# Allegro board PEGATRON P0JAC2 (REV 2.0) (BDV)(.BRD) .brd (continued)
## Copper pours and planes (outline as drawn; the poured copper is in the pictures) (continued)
+VSYS on L6-GND (solid shape): 60.99,41.82 60.99,39.56 60.83,39.41 60.5,39.41 60.43,39.48 60.43,39.56 60.45,39.63 60.45,39.71 60.45,40.07 60.25,40.27 60.25,41.87 60.33,41.95 60.86,41.95
+VSYS on L6-GND (solid shape): 58.5,41.74 58.5,41.09 58.48,41.08 58.48,40.29 58.49,40.25 58.5,40.17 58.26,39.93 58.26,39.25 58.12,39.11 57.94,39.11 57.81,39.24 57.81,41.74 57.89,41.82 58.42,41.82
+VSYS on L6-GND (solid shape): 56.13,42.91 56.13,39.81 56.07,39.75 55.64,39.75 55.53,39.86 55.53,41.1 55.53,41.11 55.56,41.2 55.56,41.28 55.55,41.62 55.25,41.77 55.22,41.77 55.18,41.81 55.18,43.08 55.35,43.24 55.8,43.24
+VSYS on L6-GND (solid shape): 65.06,28.94 65.25,28.85 65.43,28.94 65.63,28.94 65.7,28.88 65.79,28.85 65.8,28.85 65.94,28.71 65.94,27.92 65.81,27.8 64.68,27.8 64.67,27.8 64.57,27.83 64.46,27.8 64.45,27.8 64.42,27.8 64.11,28.1 64.11,28.76 64.29,28.94
+VSYS_DOCKING on BOTTOM (solid shape): 25.65,28.94 25.65,27.52 25.35,27.21 23.47,27.21 23.17,27.52 23.17,29.02 23.32,29.17 25.43,29.17
+VSYS_DOCKING on BOTTOM (solid shape): 25.63,21.37 25.63,19.64 25.55,19.57 23.47,19.57 23.11,19.92 23.11,21.27 23.39,21.55 25.45,21.55
+VSYS_DOCKING on BOTTOM (solid shape): 29.69,17.21 29.69,16.57 29.9,16.37 30.99,16.37 31.22,16.14 31.22,14.31 31.01,14.11 30.63,14.11 30.4,13.88 30.4,12.68 29.95,12.23 28.75,12.23 28.32,12.66 28.32,17 28.73,17.41 29.49,17.41
+VSYS_DOCKING on L5-SIG (solid shape): outline of 118 points within 23.7,11.34 30.76,29.88
COMPASS_RSTN# on BOTTOM (solid shape): 67.87,117.18 67.87,117.1 67.84,117.08 67.51,117.08 67.36,116.93 67.36,114.28 67.56,114.08 68.02,114.08 68.07,114.03 68.07,113.93 68.02,113.88 67.37,113.88 67.18,114.07 67.18,116.98 67.44,117.23 67.82,117.23
EC_A_GND on BOTTOM (solid shape): 70.67,64.9 70.67,62.76 70.59,62.67 68.56,62.67 68.5,62.72 68.5,63.03 68.24,63.29 68.24,63.38 67.5,63.38 67.5,62.89 67.46,62.85 67.03,62.85 66.85,63.02 66.85,63.53 66.88,63.56 67.57,63.56 67.57,64.17 68.23,64.17 69.14,63.26 70.38,63.26 70.45,63.32 70.45,64.92 70.65,64.92
GYRO_IRQ_R on BOTTOM (solid shape): 29.9,100.54 30.56,100.54 30.66,100.44 30.66,100.29 30.61,100.24 28.83,100.24 28.8,100.26 28.8,100.95 28.83,100.97 29.46,100.97
GYRO_REGOUT on BOTTOM (solid shape): 30.73,99.63 30.73,99.45 29.69,99.45 29.31,99.07 28.88,99.07 28.83,99.12 28.83,99.65 28.91,99.73 30.63,99.73
I2C_4_SCL on BOTTOM (solid shape): 34.65,99.02 34.65,98.59 34.57,98.51 33.81,98.51 33.68,98.64 32.89,98.64 32.87,98.66 32.87,98.89 32.92,98.94 34.01,98.94 34.16,99.1 34.57,99.1
I2C_4_SDA on BOTTOM (solid shape): 33.58,98.38 34.57,98.38 34.65,98.31 34.65,97.77 34.04,97.77 33.6,98.21 33.02,98.21 32.97,98.26 32.97,98.49 33,98.51 33.45,98.51
LCDVDD_EN_R on BOTTOM (solid shape): 56.26,16.39 56.26,15.73 56.16,15.63 55.58,15.63 55.42,15.48 55.42,14.26 55.35,14.18 54.36,14.18 54.26,14.28 54.26,16.24 54.51,16.49 56.16,16.49
LED_AN on BOTTOM (solid shape): 50.11,6.16 50.11,4.18 50.42,3.87 50.42,2.75 50.32,2.65 49.58,2.65 49.48,2.75 49.48,3.72 49.25,3.95 48.69,3.95 48.51,3.77 48.51,2.42 48.27,2.18 46.77,2.18 46.69,2.27 46.69,3.69 47.09,4.1 48.13,4.1 48.64,4.61 48.64,6.08 48.82,6.26 50.01,6.26
LVDS_A_GND on L7-SIG (solid shape): outline of 388 points within 64.57,12.05 76.33,21.79
PMID on BOTTOM (solid shape): 37.14,22.72 37.25,22.72 37.45,22.67 37.64,22.72 38.05,22.72 38.33,22.44 39.35,22.44 39.45,22.34 39.45,21.73 39.37,21.65 38.08,21.65 37.85,21.88 37.85,22.08 37.72,22.21 36.68,22.21 36.32,22.56 35.66,22.56 35.66,22.82 37.03,22.82
REGN on BOTTOM (solid shape): 38.58,23.5 38.58,22.79 38.56,22.77 38.2,22.77 38.05,22.92 37.24,22.92 37.11,23.05 35.64,23.05 35.64,23.3 36.4,23.3 36.65,23.56 38.53,23.56
SPEAKER_OUT_LN on BOTTOM (solid shape): 30.91,63.43 31.25,63.43 31.42,63.61 31.7,63.61 31.77,63.6 31.93,63.61 31.93,63.61 32.18,63.61 32.27,63.53 32.27,62.99 32.12,62.84 30.67,62.84 30.1,63.4 30.1,63.65 30.69,63.65
SPEAKER_OUT_LP on BOTTOM (solid shape): 29.99,63.12 30.21,63.12 30.61,62.71 31.14,62.71 31.4,62.63 31.65,62.71 32.19,62.71 32.39,62.52 32.39,62.06 32.13,61.81 30.89,61.81 30.74,61.66 30.64,61.66 30.38,61.4 30.11,61.4 29.66,61.85 29.66,63.19 29.91,63.19
SPEAKER_OUT_RP on BOTTOM (solid shape): 32.45,65.58 32.45,64.83 32.36,64.74 32.36,64.4 32.31,64.35 31.95,64.35 31.67,64.63 31.5,64.63 30.1,64.63 30.1,64.86 31.06,64.86 31.29,65.08 31.29,65.08 31.85,65.64 32.4,65.64
SPI_CS# on BOTTOM (solid shape): 14.25,75.19 14.25,74.55 14.22,74.51 14.02,74.51 13.99,74.55 13.99,75.05 13.94,75.1 13.15,75.1 12.99,75.27 12.99,75.47 13.14,75.63 13.82,75.63
SPI_CS#_CON on BOTTOM (solid shape): 15.13,75.65 15.13,75.27 14.91,75.05 14.82,75.05 14.82,74.02 14.82,73.35 14.8,73.33 14.5,73.33 14.45,73.38 14.45,74.23 14.48,74.26 14.48,75.55 14.65,75.71 15.06,75.71
N43112359 on BOTTOM (solid shape): 73.05,41.46 73.91,41.46 74.17,41.21 74.17,40.85 74.45,40.57 75.72,40.57 76.07,40.93 76.07,41.41 76.2,41.54 76.58,41.54 76.73,41.39 76.73,40.85 77.42,40.17 77.42,37.04 76.72,36.34 73.55,36.34 73.38,36.51 73.38,36.92 73.03,37.27 73.03,39.84 72.47,40.39 72.48,40.69 72.29,40.92 72.29,41.69 72.31,41.72 72.8,41.72
N43112762 on BOTTOM (solid shape): 81.61,42.78 81.61,36.38 81.2,35.98 78.03,35.98 77.8,36.2 77.8,39.76 79.1,41.06 79.1,42.88 79.2,42.99 81.41,42.99
N45929927 on BOTTOM (solid shape): 75.19,42.88 75.19,42.45 75.39,42.25 75.87,42.25 75.95,42.17 75.95,41.89 75.85,41.79 73.76,41.79 73.71,41.84 73.71,42.35 73.84,42.48 73.84,42.96 73.91,43.04 75.03,43.04
N54799847 on BOTTOM (solid shape): 70.25,42.52 70.25,41.87 70.35,41.77 70.84,41.77 70.92,41.69 70.92,41.26 70.87,41.21 69.42,41.21 69.24,41.39 69.24,42.53 69.39,42.67 70.09,42.67
N57840224 on BOTTOM (solid shape): 77.79,23.12 77.79,21.8 77.39,21.4 77.39,21.02 77.25,20.88 77.19,20.68 77.12,20.61 75.57,20.61 75.36,20.81 75.36,23.33 75.57,23.53 77.38,23.53
N57908913 on BOTTOM (solid shape): outline of 123 points within 88.96,36.81 90.42,49.57
N58054896 on BOTTOM (solid shape): 39.62,31.07 39.62,27.57 39.42,27.37 38.53,27.37 37.97,26.81 37.97,25.03 37.72,24.77 36.73,24.77 35.99,24.04 35.64,24.04 35.56,24.11 35.56,25.13 36.23,25.8 36.23,29.71 37.73,31.21 39.49,31.21
N58054900 on BOTTOM (solid shape): 37.34,24.52 37.34,23.91 37.16,23.73 36.53,23.73 36.35,23.56 35.61,23.56 35.61,23.78 36.09,23.78 36.91,24.6 37.26,24.6
N58054916 on BOTTOM (solid shape): 33.35,28.61 33.35,25.05 33.27,24.98 31.4,24.98 31.17,25.21 31.17,27.31 30.94,27.54 29.39,27.54 29.24,27.7 29.24,28.76 29.36,28.89 33.07,28.89
N58056974 on BOTTOM (solid shape): 46.71,6.72 46.71,5.09 46.48,4.86 46.03,4.86 45.9,4.73 45.9,4 46.28,3.62 46.28,2.4 46.05,2.17 44.5,2.17 43.61,3.06 43.61,7.4 43.76,7.55 45.87,7.55
N58057069 on BOTTOM (solid shape): 48.59,7.71 48.59,6.66 48.18,6.26 47.22,6.26 46.89,6.59 46.89,7.81 47.09,8.01 48.29,8.01
N58057069 on BOTTOM (solid shape): 44.6,23.23 44.6,22.72 44.93,22.39 46.13,22.39 46.34,22.18 46.34,21.93 46.59,21.93 46.69,21.83 47.78,21.83 47.93,21.68 47.93,20.53 47.6,20.2 46.18,20.2 45.82,20.56 44.4,20.56 44.15,20.81 44.15,22.26 44.34,22.45 44.34,23.34 44.35,23.35 44.48,23.35
N58057069 on L2-SIG (solid shape): 47.88,21.17 47.88,18.88 47.52,18.53 46.53,18.53 45.92,19.14 45.92,20.99 46.28,21.35 47.7,21.35
N58057069 on L2-SIG (solid shape): 48.74,7.96 48.74,6.61 48.51,6.39 47.88,6.39 47.57,6.69 47.57,7.93 47.75,8.11 48.59,8.11
N58057081 on BOTTOM (solid shape): 46.05,19.47 46.05,18.5 45.72,18.17 44.04,18.17 43.94,18.27 43.33,18.27 42.98,17.92 39.42,17.92 39.27,18.07 39.27,18.91 39.4,19.03 39.7,19.03 40.82,20.15 45.37,20.15
N58057187 on BOTTOM (solid shape): 47.78,19.77 47.78,18.7 47.45,18.37 46.61,18.37 46.41,18.58 46.41,19.87 46.48,19.95 47.6,19.95
N59826746 on BOTTOM (solid shape): 34.67,100.59 34.67,100.06 34.6,99.98 34.16,99.98 34.01,99.83 32.92,99.83 32.89,99.86 32.89,100.11 32.92,100.14 33.83,100.14 34.04,100.34 34.04,100.52 34.14,100.62 34.65,100.62
N59826750 on BOTTOM (solid shape): 34.67,99.81 34.67,99.25 34.65,99.22 34.6,99.22 34.11,99.22 33.96,99.07 32.89,99.07 32.89,99.3 32.92,99.32 33.68,99.32 33.88,99.53 33.89,99.53 34.22,99.86 34.62,99.86
N59826757 on BOTTOM (solid shape): 30.76,99.3 30.76,99.02 30.73,98.99 29.89,98.99 29.49,98.59 29.49,98.41 29.39,98.31 28.88,98.31 28.8,98.38 28.8,98.87 28.88,98.94 29.36,98.94 29.42,99 29.43,99.01 29.74,99.32 30.73,99.32
N60244404 on BOTTOM (solid shape): 76.96,51.83 76.96,50.35 76.78,50.17 75.41,50.17 75.26,50.33 75.26,51.9 75.36,52 76.78,52
N60244404 on BOTTOM (solid shape): 85.13,56.3 85.48,56.3 85.49,56.3 85.82,56.3 85.85,56.27 85.85,54.32 85.47,53.94 85.11,53.94 84.83,54.22 84.83,56.27 84.86,56.3 85.12,56.3
N60244404 on L7-SIG (solid shape): 77.19,51.84 77.19,50.37 76.91,50.1 75.69,50.1 75.49,50.3 75.49,51.8 75.77,52.08 76.94,52.08
N60244404 on L7-SIG (solid shape): 85.73,55.97 85.73,55.01 85.62,54.9 84.33,54.9 84.18,55.05 84.18,56.04 84.29,56.14 85.55,56.14
N60946431 on L7-SIG (solid shape): 33.12,16.98 33.12,16.09 33,15.96 31.55,15.96 31.42,16.09 31.42,16.98 31.52,17.08 33.02,17.08
N60977672 on BOTTOM (solid shape): 24.98,52.55 24.98,48.76 24.83,48.61 23.54,48.61 23.37,48.78 23.37,49.72 23.05,50.04 23.05,52.49 23.25,52.68 24.85,52.68
N60977672 on L7-SIG (solid shape): 28.19,47.36 29.57,47.36 29.64,47.28 29.64,46.47 29.59,46.42 24.94,46.42 24.16,47.2 24.16,48.37 24.08,48.45 23.52,48.45 23.37,48.59 23.37,50.31 23.57,50.5 25.05,50.5
N61060018 on BOTTOM (solid shape): 71.86,42.91 71.86,41.26 71.81,41.21 71.5,41.21 71.45,41.26 71.45,41.64 71.17,41.92 70.92,41.92 70.79,42.05 70.79,42.94 70.87,43.01 71.76,43.01
N61060048 on BOTTOM (solid shape): 73.05,45.93 73.05,45.5 73.32,45.23 73.32,44.88 73.28,44.84 72.8,44.84 72.67,44.97 72.67,45.35 72.49,45.53 71.96,45.53 71.78,45.35 71.78,44.41 71.43,44.41 71.43,45.22 71.25,45.4 71.25,46.34 71.37,46.47 72.52,46.47
N61684486 on BOTTOM (solid shape): 76.15,84.49 76.15,83.98 75.97,83.8 74.19,83.8 74.02,83.63 74.02,82.61 73.94,82.53 73.53,82.53 73.41,82.66 73.41,84.36 73.64,84.59 76.05,84.59
N61684936 on BOTTOM (solid shape): 79.96,84.41 79.96,82.64 79.86,82.53 79.4,82.53 79.27,82.66 79.27,83.7 79.07,83.91 78.05,83.91 77.98,83.98 77.98,84.46 78,84.49 79.88,84.49
N61684944 on BOTTOM (solid shape): 79.25,82.31 79.96,82.31 80.01,82.25 80.01,81.7 79.96,81.65 78.21,81.65 77.95,81.9 77.95,82.59 78.97,82.59
N61684969 on BOTTOM (solid shape): 76.1,82.48 76.1,81.82 75.9,81.62 73.48,81.62 73.43,81.67 73.43,82 73.48,82.05 74.55,82.05 75.06,82.56 76.02,82.56
N62009177 on BOTTOM (solid shape): 70.46,51.65 70.46,51.09 70.36,50.99 69.39,50.99 69.29,51.09 69.29,51.8 69.34,51.85 70.26,51.85
N62692739 on BOTTOM (solid shape): 68.78,9.94 68.78,9.13 68.61,8.95 66.47,8.95 66.35,9.08 66.35,9.94 66.42,10.02 68.71,10.02

Small or netless copper shapes (teardrops, artwork), in the pictures only: 12 on TOP, 525 on BOTTOM, 211 on L2-SIG, 464 on L3-GND, 528 on L4-SIG, 1014 on L5-SIG, 1705 on L6-GND, 1629 on L7-SIG

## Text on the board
